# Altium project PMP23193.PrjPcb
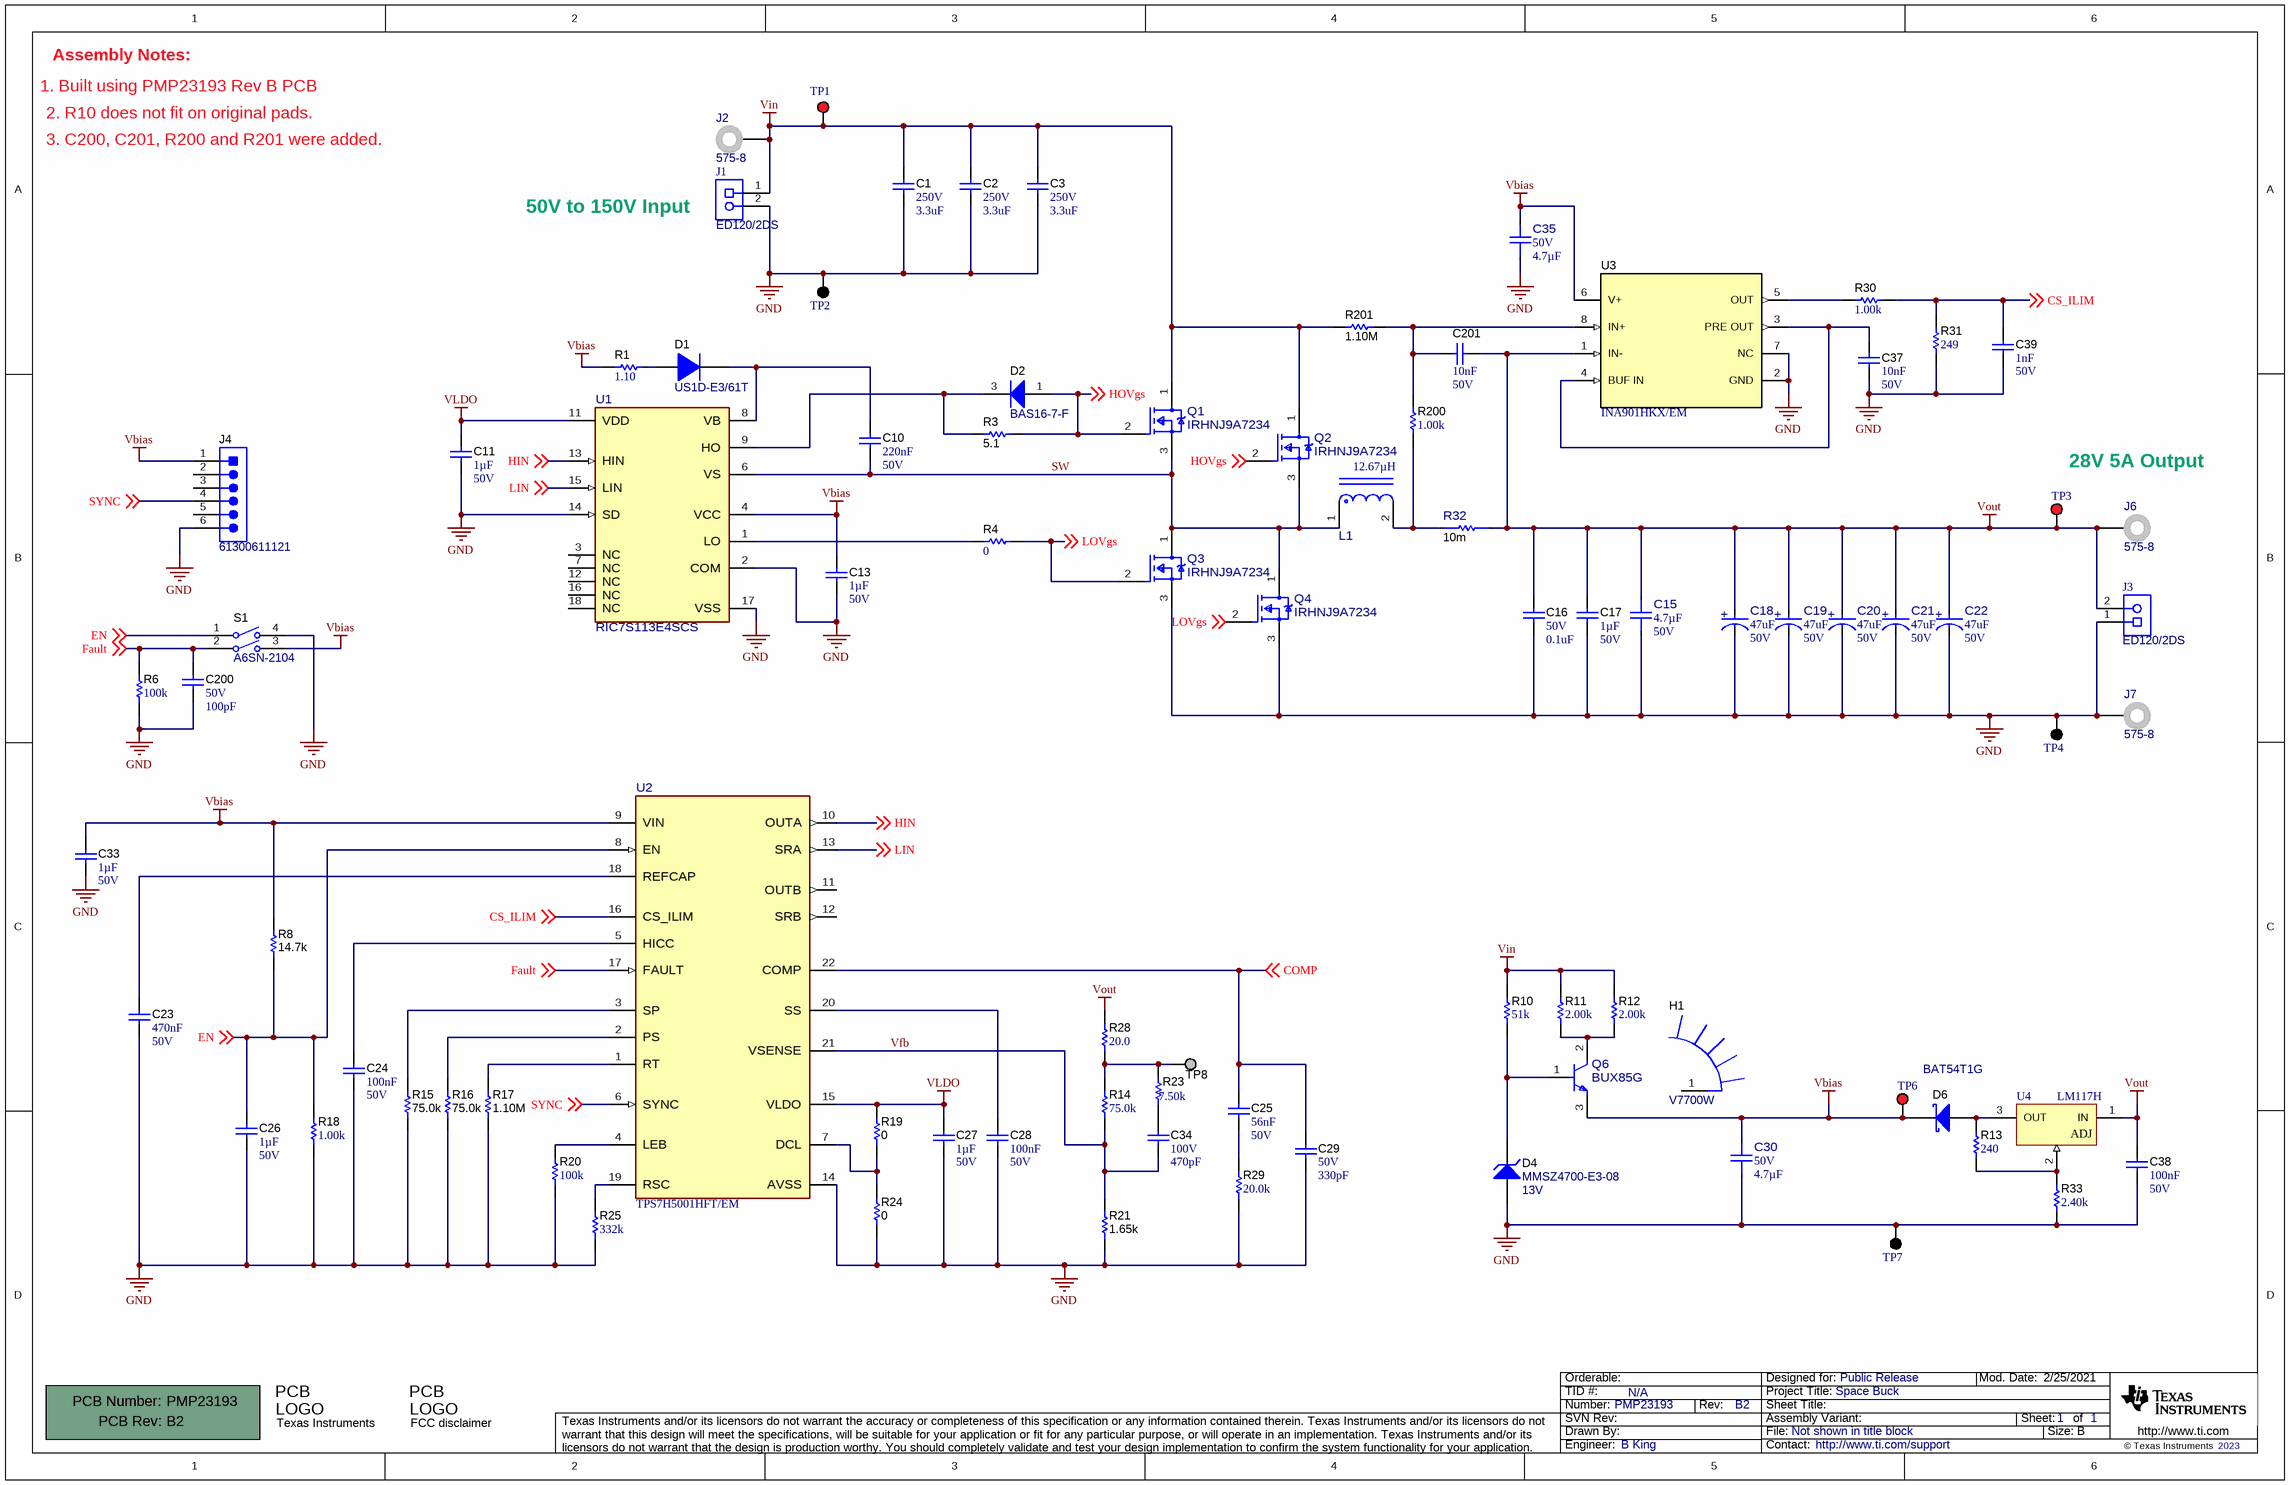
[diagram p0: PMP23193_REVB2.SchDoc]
TID: N/A; TechSupport: http://www.ti.com/support; SCH_Rev: B2; PRJ_Title: Space Buck; PRJ_Number: PMP23193; PRJ_Engineer: B King; PRJ_Customer: Public Release; PCB_Rev: B2; PCB_Layout: B King; CopyrightYear: 2023
1 sheet, 90 parts. Net scope: global (net labels, ports and power ports of the same name join across sheets).
Board file: PMP23193_REVB.PcbDoc

## Sheet PMP23193_REVB2.SchDoc
size 431 x 279 mm; Date: Not shown in title block; ApprovedBy: Not shown in title block; CheckedBy: Not shown in title block; Author: Not shown in title block; CompanyName: Not shown in title block; Engineer: Not shown in title block; Organization: Not shown in title block; Address1: Not shown in title block; Address2: Not shown in title block; Address3: Not shown in title block; Address4: Not shown in title block; DocumentNumber: 1; Revision: Use project parameter SCH_Rev; SheetNumber: 1; SheetTotal: 1; PageSetup: Record=PageOptions¦CenterHorizontal=True¦CenterVertical=True¦PrintScale=1.00¦XCorrection=1.00¦YCorrection=1.00¦PrintKind=0¦BorderSize=5000000¦LeftOffset=0¦BottomOffset=0¦Orientation=2¦PaperLength=1000¦PaperWidth=1000¦Scale=100¦PaperSource=15¦PrintQuality=600¦MediaType=1¦DitherType=10¦PaperKind=Letter¦PrintScaleMode=1

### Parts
!PCB1  Printed Circuit Board  (value not drawn)  (mechanical)
C1  VDC_V: 250V  ValueDisplayed: 3.3uF  [CKG57N]  (hidden comment: CKG57NX7T2E335M500JH)
C2  VDC_V: 250V  ValueDisplayed: 3.3uF  [CKG57N]  (hidden comment: CKG57NX7T2E335M500JH)
C3  VDC_V: 250V  ValueDisplayed: 3.3uF  [CKG57N]  (hidden comment: CKG57NX7T2E335M500JH)
C10  Cap_F: 220nF  VDC_V: 50V  [0805_HV]  (hidden comment: GRM21BR71H224KA01L)
C11  Cap_F: 1µF  VDC_V: 50V  [0805_HV]  (hidden comment: GCJ21BR71H105MA01L)
C13  Cap_F: 1µF  VDC_V: 50V  [0805_HV]  (hidden comment: GCJ21BR71H105MA01L)
C15  Cap_F: 4.7µF  VDC_V: 50V  [FP-CGA4J1X7R1H475K125AC_0805-MFG]  (hidden comment: CGA4J1X7R1H475K125AC)
C16  VDC_V: 50V  ValueDisplayed: 0.1uF  [0402]  (hidden comment: GCM155R71H104KE02D)
C17  Cap_F: 1µF  VDC_V: 50V  [0603]  (hidden comment: UMK107AB7105KA-T)
C18  ValueDisplayed: 47uF  VDC_V: 50V  [FP-T97N476K050HAA_SMT_CAPACITOR-MFG]  (hidden comment: T97N476K050HAA)
C19  ValueDisplayed: 47uF  VDC_V: 50V  [FP-T97N476K050HAA_SMT_CAPACITOR-MFG]  (hidden comment: T97N476K050HAA)
C20  ValueDisplayed: 47uF  VDC_V: 50V  [FP-T97N476K050HAA_SMT_CAPACITOR-MFG]  (hidden comment: T97N476K050HAA)
C21  ValueDisplayed: 47uF  VDC_V: 50V  [FP-T97N476K050HAA_SMT_CAPACITOR-MFG]  (hidden comment: T97N476K050HAA)
C22  ValueDisplayed: 47uF  VDC_V: 50V  [FP-T97N476K050HAA_SMT_CAPACITOR-MFG]  (hidden comment: T97N476K050HAA)
C23  Cap_F: 470nF  VDC_V: 50V  [0603]  (hidden comment: CGA3E3X7R1H474K080AB)
C24  Cap_F: 100nF  VDC_V: 50V  [0603]  (hidden comment: CGA3E2X7R1H104K080AA)
C25  Cap_F: 56nF  VDC_V: 50V  [0603]  (hidden comment: GRM188R71H563KA93D)
C26  Cap_F: 1µF  VDC_V: 50V  [0603]  (hidden comment: UMK107AB7105KA-T)
C27  Cap_F: 1µF  VDC_V: 50V  [0603]  (hidden comment: UMK107AB7105KA-T)
C28  Cap_F: 100nF  VDC_V: 50V  [0603]  (hidden comment: CGA3E2X7R1H104K080AA)
C29  VDC_V: 50V  ValueDisplayed: 330pF  [0603]  (hidden comment: GRM1885C1H331JA01D)
C30  VDC_V: 50V  Cap_F: 4.7µF  [FP-C2012X7R1H475K125AC_0805-MFG]  (hidden comment: C2012X7R1H475K125AC)
C33  Cap_F: 1µF  VDC_V: 50V  [0603]  (hidden comment: UMK107AB7105KA-T)
C34  VDC_V: 100V  ValueDisplayed: 470pF  [0603]  (hidden comment: GRM1885C2A471JA01D)
C35  VDC_V: 50V  Cap_F: 4.7µF  [FP-C2012X7R1H475K125AC_0805-MFG]  (hidden comment: C2012X7R1H475K125AC)
C37  Cap_F: 10nF  VDC_V: 50V  [0603]  (hidden comment: GCM188R71H103KA37D)
C38  Cap_F: 100nF  VDC_V: 50V  [0603]  (hidden comment: CGA3E2X7R1H104K080AA)
C39  Cap_F: 1nF  VDC_V: 50V  [0603]  (hidden comment: C0603C102K5RACTU)
C200  VDC_V: 50V  ValueDisplayed: 100pF  [0603]  (hidden comment: C1608C0G1H101J080AE)
C201  Cap_F: 10nF  VDC_V: 50V  [0603]  (hidden comment: GCM188R71H103KA37D)
D1  US1D-E3/61T  [SMA]
D2  BAS16-7-F  [SOT-23]
D4  MMSZ4700-E3-08  value 13V  [SOD-123]
D6  BAT54T1G  [SOD-123]
H1  V7700W  [ASMN_V7700W]
J1  ED120/2DS  [On-Shore_ED120_2DS]
J2  575-8  [Keystone575-8]
J3  ED120/2DS  [On-Shore_ED120_2DS]
J4  61300611121  [WURTH_61300611121]
J6  575-8  [Keystone575-8]
J7  575-8  [Keystone575-8]
L1  Ind_H: 12.67µH  [FP-S69833_PTH2_D1IN43-MFG]  (hidden comment: S69833)
Logo1  Texas Instruments  [TI_Stacked_Overlay_Small]  (no BOM)
Logo2  FCC disclaimer  [FCC_disclaimer]  (no BOM)
Q1  IRHNJ9A7234  [FP-IRHNJ9A7234_SMD3-MFG]
Q2  IRHNJ9A7234  [FP-IRHNJ9A7234_SMD3-MFG]
Q3  IRHNJ9A7234  [FP-IRHNJ9A7234_SMD3-MFG]
Q4  IRHNJ9A7234  [FP-IRHNJ9A7234_SMD3-MFG]
Q6  BUX85G  [FP-BUX85G_TO-220-3-MFG]
R1  ValueDisplayed: 1.10  [0603]  (hidden comment: CRCW06031R10FKEA)
R3  ValueDisplayed: 5.1  [0603]  (hidden comment: CRCW06035R10JNEA)
R4  ValueDisplayed: 0  [0603]  (hidden comment: RMCF0603ZT0R00)
R6  ValueDisplayed: 100k  [0603]  (hidden comment: RC0603FR-07100KL)
R8  ValueDisplayed: 14.7k  [0603]  (hidden comment: CRCW060314K7FKEA)
R10  ValueDisplayed: 51k  [2512]  (hidden comment: CRCW251251K0JNEG)
R11  ValueDisplayed: 2.00k  [2512]  (hidden comment: CRCW25122K00FKEG)
R12  ValueDisplayed: 2.00k  [2512]  (hidden comment: CRCW25122K00FKEG)
R13  ValueDisplayed: 240  [0603]  (hidden comment: RC0603FR-07240RL)
R14  ValueDisplayed: 75.0k  [0603]  (hidden comment: CRCW060375K0FKEA)
R15  ValueDisplayed: 75.0k  [0603]  (hidden comment: CRCW060375K0FKEA)
R16  ValueDisplayed: 75.0k  [0603]  (hidden comment: CRCW060375K0FKEA)
R17  ValueDisplayed: 1.10M  [0603]  (hidden comment: CRCW06031M10FKEA)
R18  ValueDisplayed: 1.00k  [0603]  (hidden comment: CRCW06031K00FKEA)
R19  ValueDisplayed: 0  [0603]  (hidden comment: RCS06030000Z0EA)
R20  ValueDisplayed: 100k  [0603]  (hidden comment: RC0603FR-07100KL)
R21  ValueDisplayed: 1.65k  [0603]  (hidden comment: CRCW06031K65FKEA)
R23  ValueDisplayed: 7.50k  [0603]  (hidden comment: CRCW06037K50FKEA)
R24  ValueDisplayed: 0  [0603]  (hidden comment: RCS06030000Z0EA)
R25  ValueDisplayed: 332k  [0603]  (hidden comment: CRCW0603332KFKEA)
R28  ValueDisplayed: 20.0  [0603]  (hidden comment: RC0603FR-0720RL)
R29  ValueDisplayed: 20.0k  [0603]  (hidden comment: CRCW060320K0FKEA)
R30  ValueDisplayed: 1.00k  [0603]  (hidden comment: CRCW06031K00FKEA)
R31  ValueDisplayed: 249  [0603]  (hidden comment: CRCW0603249RFKEA)
R32  value 10m  [FP-WSLP2512R0100FEA_2512-MFG]  (hidden comment: WSLP2512R0100FEA)
R33  ValueDisplayed: 2.40k  [0603]  (hidden comment: RC0603FR-072K4L)
R200  ValueDisplayed: 1.00k  [0603]  (hidden comment: CRCW06031K00FKEA)
R201  ValueDisplayed: 1.10M  [0603]  (hidden comment: CRCW06031M10FKEA)
S1  A6SN-2104  [SW_A6SN-2104]
TP1  5010  [Keystone5010]  (value not drawn)
TP2  5011  [Keystone5011]  (value not drawn)
TP3  5010  [Keystone5010]  (value not drawn)
TP4  5011  [Keystone5011]  (value not drawn)
TP6  5010  [Keystone5010]  (value not drawn)
TP7  5011  [Keystone5011]  (value not drawn)
TP8  5128  [Keystone5128]  (value not drawn)
U1  RIC7S113E4SCS  [FP-RIC7S113E4SCS_LCC18_CIC-IPC_C]
U2  TPS7H5001HFT/EM  [HFT0022A-C01-MFG]
U3  INA901HKX/EM  [HKX0008A_Custom_A]
U4  LM117H  [NDT0003A]

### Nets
GND: C1.1 C2.2 C3.2 C11.2 C13.2 C15.1 C16.2 C17.2 C18.1(CATHODE) C19.1(CATHODE) C20.1(CATHODE) C21.1(CATHODE) C22.1(CATHODE) C23.2 C24.2 C26.2 C27.2 C28.2 C29.2 C30.1 C33.2 C35.1 C37.2 C38.2 C39.2 C200.2 D4.2(A) J1.2 J3.1 J4.6 J7.1 Q3.3(SOURCE) Q4.3(SOURCE) R6.1 R15.1 R16.1 R17.1 R18.1 R20.1 R21.1 R24.1 R25.1 R29.1 R31.1 R33.1 S1.4 TP2.1 TP4.1 TP7.1 U1.2(COM) U1.14(SD) U1.17(VSS) U2.14(AVSS) U3.2(GND) U3.7(NC)
Vbias: C13.1 C30.2 C33.1 C35.2 D6.1(K) J4.1 Q6.3(E) R1.1 R8.2 S1.3 TP6.1 U1.4(VCC) U2.9(VIN) U3.6(V+)
Vin: C1.2 C2.1 C3.1 J1.1 J2.1 Q1.1(DRAIN) Q2.1(DRAIN) R10.2 R11.2 R12.2 R201.2 TP1.1
VLDO: C11.1 C27.1 R19.2 U1.11(VDD) U2.15(VLDO)
Vout: C15.2 C16.1 C17.1 C18.2(ANODE) C19.2(ANODE) C20.2(ANODE) C21.2(ANODE) C22.2(ANODE) C38.1 C201.2 J3.2 J6.1 R28.2 R32.2 TP3.1 U3.1(IN-) U4.1(IN)
COMP: C25.1 C29.1 U2.22(COMP) ; off-sheet COMP
CS_ILIM: C39.1 R30.1 R31.2 U2.16(CS_ILIM) ; off-sheet CS_ILIM
EN: C26.1 R8.1 R18.2 S1.1 U2.8(EN) ; off-sheet EN
Fault: C200.1 R6.2 S1.2 U2.17(FAULT) ; off-sheet Fault
HIN: U1.13(HIN) U2.10(OUTA) ; off-sheet HIN
HOVgs: D2.1(A) Q1.2(GATE) Q2.2(GATE) R3.2 ; off-sheet HOVgs
LIN: U1.15(LIN) U2.13(SRA) ; off-sheet LIN
LOVgs: Q3.2(GATE) Q4.2(GATE) R4.2 ; off-sheet LOVgs
SW: C10.2 L1.1 Q1.3(SOURCE) Q2.3(SOURCE) Q3.1(DRAIN) Q4.1(DRAIN) U1.6(VS)
SYNC: J4.4 U2.6(SYNC) ; off-sheet SYNC
Vfb: C34.2 R14.1 R21.2 U2.21(VSENSE)
NetC10_1: C10.1 D1.1(K) U1.8(VB)
NetC23_1: C23.1 U2.18(REFCAP)
NetC24_1: C24.1 U2.5(HICC)
NetC25_2: C25.2 R29.2
NetC28_1: C28.1 U2.20(SS)
NetC34_1: C34.1 R23.1
NetC37_1: C37.1 U3.3(PRE_OUT) U3.4(BUF_IN)
NetC201_1: C201.1 R200.2 R201.1 U3.8(IN+)
NetD1_2: D1.2(A) R1.2
NetD2_3: D2.3(K) R3.1 U1.9(HO)
NetD4_1: D4.1(K) Q6.1(B) R10.1
NetD6_2: D6.2(A) R13.2 U4.3(OUT)
NetL1_2: L1.2 R32.1 R200.1
NetQ6_2: Q6.2(C) R11.1 R12.1
NetR4_1: R4.1 U1.1(LO)
NetR13_1: R13.1 R33.2 U4.2(ADJ)
NetR14_2: R14.2 R23.2 R28.1 TP8.1
NetR15_2: R15.2 U2.3(SP)
NetR16_2: R16.2 U2.2(PS)
NetR17_2: R17.2 U2.1(RT)
NetR19_1: R19.1 R24.2 U2.7(DCL)
NetR20_2: R20.2 U2.4(LEB)
NetR25_2: R25.2 U2.19(RSC)
NetR30_2: R30.2 U3.5(OUT)

Not connected (* = marked no-connect by the designer): H1 1; J4 2 3 5; U1 3(NC) 7(NC) 12(NC) 16(NC) 18(NC); U2 11(OUTB) 12(SRB)

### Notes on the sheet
- Assembly Notes:
- 1. Built using PMP23193 Rev B PCB
- 3. C200, C201, R200 and R201 were added.
- 2. R10 does not fit on original pads.
- 50V to 150V Input
- 28V 5A Output

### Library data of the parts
!PCB1 = CMP-0003618-2: Manufacturer: Any; PartNumber: PMP23193
C1-C3 = CMP-0009427-1: CAP, CERM, 3.3 uF, 250 V, +/- 20%, X7T, AEC-Q200 Grade 1, 6x5x5mm; Manufacturer: TDK; TaMin_C: -55°C; Polarized: N; SizeAreaWB_mm2: 56; Value1: Unknown; U/M: EA; Value: 3.3uF; TaMax_C: 125°C; SizeZ_mm: 5.5; SizeX_mm: 6; SizeY_mm: 5; Cap_Case: 2220; SizeArea_mm2: 30; AEC Qualified: Y; Cap_F: 3.3µF; AEC Grade: 1; AEC Category: Q200
C10 = CMP-0008354-2: CAP, CERM, 0.22 uF, 50 V, +/- 10%, X7R, 0805; Manufacturer: MuRata; TaMin_C: -55°C; Polarized: N; SizeAreaWB_mm2: 6.75; Value1: Unknown; U/M: EA; Value: 0.22uF; TaMax_C: 125°C; SizeZ_mm: 1.45; SizeX_mm: 2; SizeY_mm: 1.25; Cap_Case: 0805; SizeArea_mm2: 2.5; AEC Category: Q200
C11 C13 = CMP-0080480-1: CAP, CERM, 1 µF, 50 V,+/- 20%, X7R, AEC-Q200 Grade 1, 0805; Manufacturer: MuRata; TaMin_C: -55°C; Polarized: N; SizeAreaWB_mm2: 6.75; U/M: EA; Value: 1uF; TaMax_C: 125°C; SizeZ_mm: 1.45; SizeX_mm: 2; SizeY_mm: 1.25; Cap_Case: 0805; SizeArea_mm2: 2.5; AEC Qualified: Y; AEC Grade: 1; AEC Category: Q200
C15 = CMP-0090082-1: Cap Ceramic 4.7uF 50V X7R 10% Pad SMD 0805 +125°C Automotive T/R; Manufacturer: TDK Corporation; SizeZ_mm: 1.45mm; Tolerance_%: 0.1%; AEC Qualified: Yes; TempCo: 15%; AEC Grade: Grade 1; Value: 4.7µF
C16 = CMP-0006356-2: CAP, CERM, 0.1 uF, 50 V, +/- 10%, X7R, AEC-Q200 Grade 1, 0402; Manufacturer: MuRata; TaMin_C: -55°C; Polarized: N; SizeAreaWB_mm2: 3; Value1: Unknown; U/M: EA; Value: 0.1uF; TaMax_C: 125°C; SizeZ_mm: 0.6; SizeX_mm: 1; SizeY_mm: 0.5; AEC Qualified: Y; Cap_F: 100nF; AEC Category: Q200
C17 C26 C27 C33 = CMP-0007508-5: CAP, CERM, 1 uF, 50 V, +/- 10%, X7R, 0603; Manufacturer: Taiyo Yuden; TaMin_C: -55°C; Polarized: N; SizeAreaWB_mm2: 4.68; Value1: Unknown; U/M: EA; Value: 1uF; TaMax_C: 125°C; SizeZ_mm: 1; SizeX_mm: 1.6; SizeY_mm: 0.8; SizeArea_mm2: 1.28; AEC Category: Q200
C18-C22 = CMP-0094686-1: Solid Tantalum Chip Capacitors TANTAMOUNT™, Hi-Rel COTS, Ultra-Low ESR, Conformal Coated Case; Manufacturer: Vishay; Esr: 0.15; Leakage Current: 23.5uA; SizeZ_mm: 6.8mm; Cap_F: 47µF; IRMS_A: 1.4A; Tolerance_%: 10%; Value: 47µF; Dissipation Factor: 6%; AEC Qualified: No
C23 = CMP-0007096-4: CAP, CERM, 0.47 uF, 50 V, +/- 10%, X7R, AEC-Q200 Grade 1, 0603; Manufacturer: TDK; TaMin_C: -55°C; ESR_ohm: 0.01064; Polarized: N; SizeAreaWB_mm2: 4.68; Value1: 0.01064 ohm; U/M: EA; Value: 0.47uF; TaMax_C: 125°C; SizeZ_mm: 1; SizeX_mm: 1.6; SizeY_mm: 0.8; SizeArea_mm2: 1.28; AEC Qualified: Y; IRMS_A: 1.59966A; AEC Category: Q200
C24 C28 C38 = CMP-0007078-4: CAP, CERM, 0.1 uF, 50 V, +/- 10%, X7R, AEC-Q200 Grade 1, 0603; Manufacturer: TDK; TaMin_C: -55°C; ESR_ohm: 0.0296; Polarized: N; SizeAreaWB_mm2: 4.68; Value1: 0.0296 ohm; U/M: EA; Value: 0.1uF; TaMax_C: 125°C; SizeZ_mm: 1; SizeX_mm: 1.6; SizeY_mm: 0.8; SizeArea_mm2: 1.28; AEC Qualified: Y; IRMS_A: 971.99mA; AEC Category: Q200
C25 = CMP-0007460-1: CAP, CERM, 0.056 uF, 50 V, +/- 10%, X7R, 0603; Manufacturer: MuRata; TaMin_C: -55°C; Polarized: N; SizeAreaWB_mm2: 4.68; Value1: Unknown; U/M: EA; TaMax_C: 125°C; SizeZ_mm: 1; SizeX_mm: 1.6; SizeY_mm: 0.8; SizeArea_mm2: 1.28; AEC Category: Q200
C29 = CMP-0007209-4: CAP, CERM, 330 pF, 50 V, +/- 5%, C0G/NP0, 0603; Manufacturer: MuRata; TaMin_C: -55°C; Polarized: N; SizeAreaWB_mm2: 4.68; Value1: Unknown; U/M: EA; Value: 330pF; TaMax_C: 125°C; SizeZ_mm: 1; SizeX_mm: 1.6; SizeY_mm: 0.8; SizeArea_mm2: 1.28; AEC Category: Q200
C30 C35 = CMP-0088943-1: 4.7µF ±10% 50V Ceramic Capacitor X7R 0805 (2012 Metric); Manufacturer: TDK; TempCo: 15%; AEC Qualified: No; ValueDisplayed: 4.7uF; SizeZ_mm: 1.5mm
C34 = CMP-0007272-3: CAP, CERM, 470 pF, 100 V, +/- 5%, C0G/NP0, 0603; Manufacturer: MuRata; TaMin_C: -55°C; Polarized: N; SizeAreaWB_mm2: 4.68; Value1: Unknown; U/M: EA; Value: 470pF; TaMax_C: 125°C; SizeZ_mm: 1; SizeX_mm: 1.6; SizeY_mm: 0.8; SizeArea_mm2: 1.28; AEC Category: Q200
C37 C201 = CMP-0007143-4: CAP, CERM, 0.01 uF, 50 V, +/- 10%, X7R, AEC-Q200 Grade 1, 0603; Manufacturer: MuRata; TaMin_C: -55°C; Polarized: N; SizeAreaWB_mm2: 4.68; Value1: Unknown; U/M: EA; Value: 0.01uF; TaMax_C: 125°C; SizeZ_mm: 1; SizeX_mm: 1.6; SizeY_mm: 0.8; SizeArea_mm2: 1.28; AEC Qualified: Y; AEC Category: Q200
C39 = CMP-0006847-4: CAP, CERM, 1000 pF, 50 V, +/- 10%, X7R, 0603; Manufacturer: Kemet; TaMin_C: -55°C; Polarized: N; SizeAreaWB_mm2: 4.68; Value1: Unknown; U/M: EA; Value: 1000pF; TaMax_C: 125°C; SizeZ_mm: 1; SizeX_mm: 1.6; SizeY_mm: 0.8; SizeArea_mm2: 1.28; AEC Category: Q200
C200 = CMP-0006989-4: CAP, CERM, 100 pF, 50 V, +/- 5%, C0G/NP0, 0603; Manufacturer: TDK; TaMin_C: -55°C; Polarized: N; SizeAreaWB_mm2: 4.68; Value1: Unknown; U/M: EA; Value: 100pF; TaMax_C: 125°C; SizeZ_mm: 1; SizeX_mm: 1.6; SizeY_mm: 0.8; SizeArea_mm2: 1.28; AEC Category: Q200
D1 = CMP-0029189-2: Diode, Ultrafast, 200 V, 1 A, AEC-Q101, SMA; Manufacturer: Vishay-Semiconductor; AEC Category: Q101; Vr_V: 200V; TJmax_C: 150°C; SizeAreaWB_mm2: 37.3428; SizeY_mm: 2.92; SizeX_mm: 5.59; Value1: 1A; AEC Qualified: Y; Value2: 1V; Value: 200V; SizeArea_mm2: 16.3228; SizeZ_mm: 2.87
D2 = CMP-0029005-1: Diode, Ultrafast, 75 V, 0.3 A, SOT-23; Manufacturer: Diodes Inc.; Io_A: 300mA; Green_Lifecycle: Active; SizeAreaWB_mm2: 14; Vr_V: 75V; Green_REACh: Passed; Value1: 0.3A; U/M: EA; Value: 75V; SizeZ_mm: 1.1; SizeX_mm: 2.5; SizeY_mm: 3; Vf_V: 1.125V; SizeArea_mm2: 7.5; AEC Category: Q101
D4 = CMP-0077610-3: Diode, Zener, 13 V, 500 mW, SOD-123; Manufacturer: Vishay-Semiconductor; SizeAreaWB_mm2: 13.095; AEC Qualified: N; Value1: 0.5W; RJA_CperW: 340; SizeArea_mm2: 6.545; SizeY_mm: 1.7; Power_W: 500mW; AEC Category: Q101; SizeX_mm: 3.85; SizeZ_mm: 1.35
D6 = CMP-0028457-1: Diode, Schottky, 30 V, 0.2 A, SOD-123; Manufacturer: ON Semiconductor; Io_A: 200mA; Green_Lifecycle: Not Set; SizeAreaWB_mm2: 13.095; Vr_V: 30V; Green_REACh: Incomplete; Value1: 0.2A; TJmax_C: 125°C; U/M: EA; Value: 30V; SizeZ_mm: 1.35; SizeX_mm: 3.85; SizeY_mm: 1.7; Vf_V: 800mV; Value2: 0.8V; SizeArea_mm2: 6.545; AEC Category: Q101; RJC_CperW: 174
H1 = CMP-0067644-1: Heatsink SOT-32, TO-220; Manufacturer: Assman WSW
J1 J3 = CMP-0074910-1: Terminal Block, 5.08 mm, 2x1, Brass, TH; Manufacturer: On-Shore Technology; Cert_VDE: Y; CNHeader: False; Current_A: 15A; Green_Lifecycle: Not Set; Shrouded: N; Gender: Female; Green_REACh: Incomplete; Voltage_V: 300V; Row_Count: 1; Pitch_mm: 5.08; CT: True
J2 J6 J7 = CMP-0055166-1: Standard Banana Jack, Uninsulated, 8.9mm; Manufacturer: Keystone; CT: TRUE; Green_REACh: Passed; CNHeader: FALSE; Green_Lifecycle: Active
J4 = CMP-0054801-1: Header, 2.54 mm, 6x1, Gold, TH; Manufacturer: Wurth Elektronik; CNHeader: TRUE; CT: FALSE
L1 = CMP-0094619-1: 500kHz DC Inductor for PMP23139; Manufacturer: Renco Electronics; DCR_ohm: 4.29m; SizeZ_mm: 0.75inch; Tolerance_%: 10%; AEC Qualified: No; Value: 12.67uH
Logo1 = CMP-0074838-1: Texas Instrument Corporate Signature; SymbolCreator: a0412235; Lib Reference: TI_Logo; Library Reference: Logo
Logo2 = CMP-0074847-1: FCC_disclaimer; Library Reference: Logo
Q1-Q4 = CMP-0094197-1: Rad hard, 250V, 17A, single, N-channel MOSFET, R9 in a SMD-0.5 package; Manufacturer: Infineon; Turn On Delay Time: 25ns; Input Capacitace At Vds: 1510pF @ 25V; QgTyp_nC: 34nC @ 12V; Reverse Recovery Time: 335ns; Threshold Vgs Max: 4V; Reverse Recovery Charge: 3600nC; VdsMax_V: 1.2V; Power_W: 75W; Number Of Channels: 1; SizeZ_mm: 3.12mm; Rdson45_ohm: 0.11; Pulse Drain Current: 68A; AEC Qualified: No; TJmax_C: +150°C; Turn Off Delay Time: 50ns; ChMode: False; Vgs_V: 20V; Threshold Vgs Min: 2V
Q6 = CMP-0094657-1: Bipolar (BJT) Transistor NPN 450 V 2 A 4MHz 50 W Through Hole TO-220; Manufacturer: On Semiconductor; Emitter Base Voltage: 5V; Vcesat1_V: 1V; Rthja Max: 62.5°C/W; NPN: 1; TJmax_C: +150°C; SizeZ_mm: 19.85mm; Ciiva Ids: 2558954; AEC Qualified: No; Vceo_V: 450V; Import Ts: 1521844919; Fall Time Tf: 0.3us; Hfe Min: 30; Standoff Height: 2.8mm; Hfe Ss Testic: 0.1A; Power_W: 50W; IcRated_A: 3A; Value: 450V
R1 = CMP-0022174-4: RES, 1.10, 1%, 0.1 W, AEC-Q200 Grade 0, 0603; Manufacturer: Vishay-Dale; Power_W: 100mW; TempCo: 100 ppm/C; Value_Code: 1R10; Value: 1.10; EIA_Code: E96; Res_ohm: 1.1; SizeX_mm: 1.6; SizeY_mm: 0.8; SizeZ_mm: 1; Value2: 0.1W; SizeArea_mm2: 1.28; AEC Qualified: Y; VDC_V: 75V; AEC Category: Q200; AEC Grade: 0
R3 = CMP-0025834-4: RES, 5.1, 5%, 0.1 W, AEC-Q200 Grade 0, 0603; Manufacturer: Vishay-Dale; Power_W: 100mW; TempCo: 200 ppm/C; Value_Code: 5R10; Value: 5.1; EIA_Code: E24; SizeX_mm: 1.6; SizeY_mm: 0.8; SizeZ_mm: 1; Value2: 0.1W; SizeArea_mm2: 1.28; AEC Qualified: Y; VDC_V: 75V; AEC Category: Q200; AEC Grade: 0
R4 = CMP-0023343-3: RES, 0, 1%, 0.1 W, AEC-Q200 Grade 0, 0603; Manufacturer: Stackpole Electronics Inc; Power_W: 100mW; TempCo: ppm/C; U/M: EA; Value: 0; SizeX_mm: 1.6; SizeY_mm: 0.8; SizeZ_mm: 1; Value2: 0.1W; SizeArea_mm2: 1.28; AEC Qualified: Y; AEC Category: Q200
R6 R20 = CMP-0022735-5: RES, 100 k, 1%, 0.1 W, 0603; Manufacturer: Yageo; Power_W: 100mW; TempCo: 100 ppm/C; Value: 100k; EIA_Code: E96; SizeX_mm: 1.6; SizeY_mm: 0.8; SizeZ_mm: 1; Value2: 0.1W; SizeArea_mm2: 1.28; AEC Qualified: N; VDC_V: 75V; AEC Category: Q200; SizeAreaWB_mm2: 4.68
R8 = CMP-0022056-4: RES, 14.7 k, 1%, 0.1 W, AEC-Q200 Grade 0, 0603; Manufacturer: Vishay-Dale; Power_W: 100mW; TempCo: 100 ppm/C; Value_Code: 14k7; Value: 14.7k; EIA_Code: E96; SizeX_mm: 1.6; SizeY_mm: 0.8; SizeZ_mm: 1; Value2: 0.1W; SizeArea_mm2: 1.28; AEC Qualified: Y; VDC_V: 75V; AEC Category: Q200; AEC Grade: 0
R10 = CMP-0015977-1: RES, 51 k, 5%, 1 W, AEC-Q200 Grade 0, 2512; Manufacturer: Vishay-Dale; Power_W: 1W; TempCo: 200 ppm/C; Value_Code: 51k0; U/M: EA; Value: 51k; EIA_Code: E24; SizeX_mm: 6.3; SizeY_mm: 3.2; SizeZ_mm: 0.71; SizeArea_mm2: 20.16; AEC Qualified: Y; VDC_V: 500V; AEC Grade: 0; AEC Category: Q200
R11 R12 = CMP-0015569-3: RES, 2.00 k, 1%, 1 W, AEC-Q200 Grade 0, 2512; Manufacturer: Vishay-Dale; Power_W: 1W; TempCo: 100 ppm/C; Value_Code: 2k00; Value: 2.00k; EIA_Code: E96; Res_ohm: 2k; SizeX_mm: 6.3; SizeY_mm: 3.2; SizeZ_mm: 0.71; SizeArea_mm2: 20.16; AEC Qualified: Y; VDC_V: 500V; AEC Grade: 0; AEC Category: Q200
R13 = CMP-0022938-5: RES, 240, 1%, 0.1 W, 0603; Manufacturer: Yageo; Power_W: 100mW; TempCo: 100 ppm/C; Value_Code: 240R; Value: 240; SizeX_mm: 1.6; SizeY_mm: 0.8; SizeZ_mm: 1; Value2: 0.1W; SizeArea_mm2: 1.28; AEC Qualified: N; VDC_V: 75V; AEC Category: Q200; SizeAreaWB_mm2: 4.68
R14-R16 = CMP-0022589-4: RES, 75.0 k, 1%, 0.1 W, AEC-Q200 Grade 0, 0603; Manufacturer: Vishay-Dale; Power_W: 100mW; TempCo: 100 ppm/C; Value_Code: 75k0; Value: 75.0k; EIA_Code: E96; Res_ohm: 75k; SizeX_mm: 1.6; SizeY_mm: 0.8; SizeZ_mm: 1; Value2: 0.1W; SizeArea_mm2: 1.28; AEC Qualified: Y; VDC_V: 75V; AEC Category: Q200; AEC Grade: 0
R17 R201 = CMP-0022142-4: RES, 1.10 M, 1%, 0.1 W, AEC-Q200 Grade 0, 0603; Manufacturer: Vishay-Dale; Power_W: 100mW; TempCo: 100 ppm/C; Value_Code: 1M10; Value: 1.10Meg; EIA_Code: E96; Res_ohm: 1.1M; SizeX_mm: 1.6; SizeY_mm: 0.8; SizeZ_mm: 1; Value2: 0.1W; SizeArea_mm2: 1.28; AEC Qualified: Y; VDC_V: 75V; AEC Category: Q200; AEC Grade: 0
R18 R30 R200 = CMP-0022109-5: RES, 1.00 k, 1%, 0.1 W, AEC-Q200 Grade 0, 0603; Manufacturer: Vishay-Dale; Power_W: 100mW; TempCo: 100 ppm/C; Value_Code: 1k00; Value: 1.00k; EIA_Code: E96; Res_ohm: 1k; SizeX_mm: 1.6; SizeY_mm: 0.8; SizeZ_mm: 1; Value2: 0.1W; SizeArea_mm2: 1.28; AEC Qualified: Y; VDC_V: 75V; AEC Category: Q200; AEC Grade: 0
R19 R24 = CMP-0081973-1: RES, 0, 0%, 0.25 W, AEC-Q200 Grade 0, 0603; Manufacturer: Vishay-Dale; SizeAreaWB_mm2: 4.68; SizeArea_mm2: 1.28; AEC Qualified: Y; AEC Category: Q200; Value: 0; SizeZ_mm: 1; SizeY_mm: 0.8; Power_W: 250mW; Value2: 0.25W; SizeX_mm: 1.6
R21 = CMP-0022130-4: RES, 1.65 k, 1%, 0.1 W, AEC-Q200 Grade 0, 0603; Manufacturer: Vishay-Dale; Power_W: 100mW; TempCo: 100 ppm/C; Value_Code: 1k65; Value: 1.65k; EIA_Code: E96; SizeX_mm: 1.6; SizeY_mm: 0.8; SizeZ_mm: 1; Value2: 0.1W; SizeArea_mm2: 1.28; AEC Qualified: Y; VDC_V: 75V; AEC Category: Q200; AEC Grade: 0
R23 = CMP-0022601-2: RES, 7.50 k, 1%, 0.1 W, 0603; Manufacturer: Vishay-Dale; Power_W: 100mW; TempCo: 100 ppm/C; Value_Code: 7k50; U/M: EA; Value: 7.50k; EIA_Code: E96; Res_ohm: 7.5k; SizeX_mm: 1.6; SizeY_mm: 0.8; SizeZ_mm: 1; Value2: 0.1W; SizeArea_mm2: 1.28; VDC_V: 75V; AEC Category: Q200
R25 = CMP-0022336-2: RES, 332 k, 1%, 0.1 W, 0603; Manufacturer: Vishay-Dale; Power_W: 100mW; TempCo: 100 ppm/C; U/M: EA; Value: 332k; EIA_Code: E96; SizeX_mm: 1.6; SizeY_mm: 0.8; SizeZ_mm: 1; Value2: 0.1W; SizeArea_mm2: 1.28; VDC_V: 75V; AEC Category: Q200
R28 = CMP-0022908-4: RES, 20.0, 1%, 0.1 W, 0603; Manufacturer: Yageo; Power_W: 100mW; TempCo: 100 ppm/C; Value_Code: 20R0; Value: 20.0; EIA_Code: E96; Res_ohm: 20; SizeX_mm: 1.6; SizeY_mm: 0.8; SizeZ_mm: 1; Value2: 0.1W; SizeArea_mm2: 1.28; AEC Qualified: N; VDC_V: 75V; AEC Category: Q200; SizeAreaWB_mm2: 4.68
R29 = CMP-0022204-4: RES, 20.0 k, 1%, 0.1 W, AEC-Q200 Grade 0, 0603; Manufacturer: Vishay-Dale; Power_W: 100mW; TempCo: 100 ppm/C; Value_Code: 20k0; Value: 20.0k; EIA_Code: E96; Res_ohm: 20k; SizeX_mm: 1.6; SizeY_mm: 0.8; SizeZ_mm: 1; Value2: 0.1W; SizeArea_mm2: 1.28; AEC Qualified: Y; VDC_V: 75V; AEC Category: Q200; AEC Grade: 0
R31 = CMP-0022235-5: RES, 249, 1%, 0.1 W, AEC-Q200 Grade 0, 0603; Manufacturer: Vishay-Dale; Power_W: 100mW; TempCo: 100 ppm/C; Value_Code: 249R; Value: 249; EIA_Code: E96; SizeX_mm: 1.6; SizeY_mm: 0.8; SizeZ_mm: 1; Value2: 0.1W; SizeArea_mm2: 1.28; AEC Qualified: Y; VDC_V: 75V; AEC Category: Q200; AEC Grade: 0
R32 = CMP-0091402-1: 10 mOhms ±1% 3W Chip Resistor 2512 (6432 Metric) Anti-Sulfur, Automotive AEC-Q200, Current Sense, Moisture Resistant, Pulse Withstanding Metal Element; Manufacturer: Vishay; TempCo: 75ppm/°C; AEC Qualified: Yes; SizeZ_mm: 0.889mm; AEC Grade: Grade 0
R33 = CMP-0022991-5: RES, 2.40 k, 1%, 0.1 W, 0603; Manufacturer: Yageo; Power_W: 100mW; TempCo: 100 ppm/C; Value_Code: 2k40; Value: 2.40k; Res_ohm: 2.4k; SizeX_mm: 1.6; SizeY_mm: 0.8; SizeZ_mm: 1; Value2: 0.1W; SizeArea_mm2: 1.28; AEC Qualified: N; VDC_V: 75V; AEC Category: Q200; SizeAreaWB_mm2: 4.68
S1 = CMP-0081262-1: Switch, Slide, 2 SPST, Off-On, 0.025 A, 24 VDC, SMT; Manufacturer: Omron Electronic Components; CurrentRating_mA: 25A; SizeAreaWB_mm2: 101.7; PositionCount: 2; SizeZ_mm: 5.55; SizeX_mm: 9.3; SizeY_mm: 7; SizeArea_mm2: 65.1; VDC_V: 24V
TP1 TP3 TP6 = CMP-0055147-1: Test Point, Multipurpose, Red, TH; Manufacturer: Keystone; CNHeader: FALSE; Green_Lifecycle: Active; Green_REACh: Passed; ContactFinish: Silver; CT: TRUE
TP2 TP4 TP7 = CMP-0055148-1: Test Point, Multipurpose, Black, TH; Manufacturer: Keystone; CNHeader: FALSE; Green_Lifecycle: Active; Green_REACh: Passed; ContactFinish: Silver; CT: TRUE
TP8 = CMP-0055159-1: Test Point, Multipurpose, Grey, TH; Manufacturer: Keystone; CNHeader: FALSE; Green_Lifecycle: Active; Green_REACh: Passed; ContactFinish: Silver; CT: TRUE
U1 = CMP-0094198-1: MOSFET DRVR 2A 2-OUT Hi/Lo Side Non-Inv 18-Pin LCC Space Level Screening; Manufacturer: Infineon; SizeZ_mm: 3.22mm; TJmax_C: +125°C; Turn On Delay Time: 120ns; Fall Time: 17ns; Rise Time: 25ns; Max Power Dissipation: 1.6W; Number Of Outputs: 2; Max Supply Voltage: 20V; Min Supply Voltage: 5V; Turn Off Delay Time: 100ns; AEC Qualified: No
U2 = CMP-0090357-2: Radiation-Hardness-Assured Si and GaN Dual Output Controller; Manufacturer: Texas Instruments; CompType: IC; SizeZ_mm: 2.428mm; AEC Qualified: No; Min Supply Voltage: 4V; Output Type: AdjustableProgrammable; TJmax_C: +125°C; Nominal Supply Current: 10-15mA; AEC Category: Q200; Max Duty Cycle: 100%; Number Of Outputs: 2; Switching Frequency: 200-4000kHz; Max Supply Voltage: 14V; Standoff Height: 0.555mm
U3 = CMP-0081563-2: Voltage Output, Unidirectional Measurement Current-Shunt Monitor, HKX0008A (CFP-8); Manufacturer: Texas Instruments; SizeZ_mm: 2.8; Rating: Space; AEC Category: Q200; CompType: IC; AEC Qualified: N
U4 = CMP-0069991-1: 3-Terminal Adjustable Regulator, 3-pin TO-39; Manufacturer: Texas Instruments; PartNumber: LM117H/NOPB; CompType: LDO IC; PackageTopMarking: NSZXYTTE# LM117HP+; PowerWise: N

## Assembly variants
001: not fitted C26 C37 C39 R19 R24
